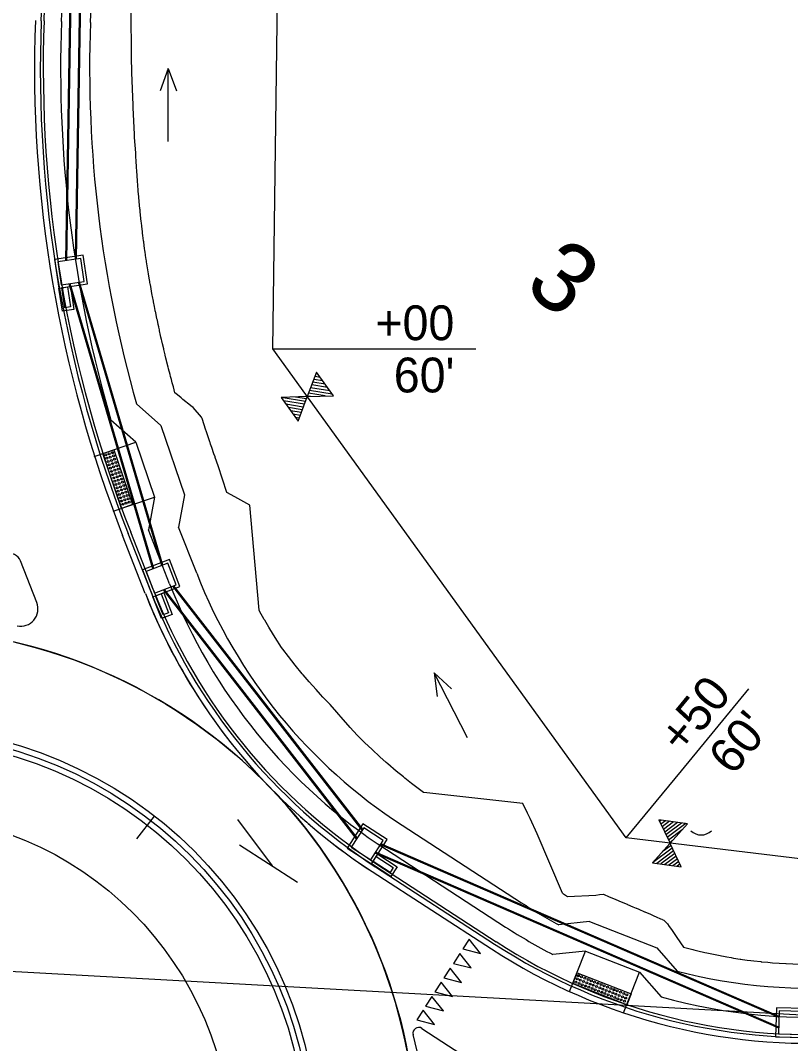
# Model space of a CAD drawing. Extents: x 670017 to 673226, y 705371 to 707498.
# Drawn here: x 671748.4 to 671881.1, y 706559.8 to 706736.1 of the extents above; entities that cross this region are included whole.
import ezdxf

# ---------------------------------------------------------------- set-up
doc = ezdxf.new("R2010")
doc.units = 0
for name, color, linetype in [('EL L 264', 7, 'Continuous'), ('EL R SCBV', 7, 'Continuous'), ('R_Drainage Flow Lines', 7, 'Continuous'), ('R_Drainage Stage 1', 7, 'Continuous'), ('R_Fence', 7, 'Continuous'), ('R_Horz Alg', 7, 'Continuous'), ('R_Horz Alg Station', 7, 'Continuous'), ('R_Horz Alg Station Annot', 7, 'Continuous'), ('R_No Plot', 7, 'Continuous'), ('R_No Plot FOC', 7, 'Continuous'), ('R_Proposed Const Limits', 7, 'Continuous'), ('R_Proposed Median', 7, 'Continuous'), ('R_Proposed RAB', 7, 'Continuous'), ('R_Proposed Road', 7, 'Continuous'), ('R_Proposed Sidewalk Stage 1', 7, 'Continuous'), ('R_ROW', 7, 'Continuous'), ('R_ROW Annot', 7, 'Continuous'), ('R_Striping', 7, 'Continuous'), ('R_Water Annot', 7, 'Continuous'), ('S_EXIST_ROW', 7, 'Continuous'), ('SS-EX-UT', 7, 'Continuous')]:
    doc.layers.add(name, color=color, linetype=linetype)

# ---------------------------------------------------------------- blocks, each defined once
blk = doc.blocks.new('FLOW ARROW')
at = {"layer": 'R_Water Annot'}
for p, q in [((-12.57, 0), (0, 0)), ((0, 0), (-3.85, 1.4)), ((0, 0), (-3.85, -1.4))]:
    blk.add_line(p, q, dxfattribs=at)

msp = doc.modelspace()

# ---------------------------------------------------------------- linework, layer by layer
at = {"layer": 'EL L 264'}
msp.add_line((671809.03, 706589.42), (671829.59, 706576.08), dxfattribs=at)
msp.add_line((671809.03, 706589.42), (671829.59, 706576.08), dxfattribs=at)
for centre, radius, start, end in [((671726.73, 706541.35), 90, 43.8918, 132.897), ((671726.73, 706541.35), 90, 43.8918, 132.897), ((671864, 706674.16), 101, 224.1964, 237.03), ((671864, 706674.16), 101, 224.1964, 237.03), ((671884.56, 706660.82), 101, 237.03, 275.3546), ((671884.56, 706660.82), 101, 237.03, 275.3546)]:
    msp.add_arc(centre, radius, start, end, dxfattribs=at)
at = {"layer": 'EL R SCBV'}
msp.add_line((671769.94, 706637.36), (671766.03, 706647.34), dxfattribs=at)
for centre, radius, start, end in [((671971.84, 706727.86), 221, 177.8657, 201.3677), ((671864, 706674.16), 101, 201.3677, 223.9093), ((671726.73, 706541.35), 90, 310.6243, 44.214)]:
    msp.add_arc(centre, radius, start, end, dxfattribs=at)
at = {"layer": 'R_Drainage Stage 1'}
for p, q in [((671756.25, 706694.69), (671759.68, 706898.95)), ((671756.42, 706694.71), (671759.85, 706898.95)), ((671757.92, 706694.94), (671761.34, 706898.93)), ((671758.09, 706694.97), (671761.51, 706898.93)), ((671772.96, 706642.24), (671758.62, 706691)), ((671771.25, 706641.57), (671756.79, 706690.72)), ((671771.4, 706641.63), (671756.96, 706690.75)), ((671772.8, 706642.18), (671758.45, 706690.98)), ((671807.32, 706596.55), (671774.68, 706638.62)), ((671807.42, 706596.7), (671774.84, 706638.68)), ((671806.36, 706595.07), (671773.06, 706637.99)), ((671806.46, 706595.22), (671773.22, 706638.05)), ((671879.17, 706564.25), (671810.46, 706594.04)), ((671879.18, 706564.43), (671810.55, 706594.18)), ((671879.12, 706562.45), (671809.54, 706592.62)), ((671879.12, 706562.63), (671809.63, 706592.76))]:
    msp.add_line(p, q, dxfattribs=at)
for points in [[(671759.99, 706690.71), (671759.23, 706695.65), (671754.29, 706694.89), (671755.05, 706689.95)], [(671759.42, 706691.13), (671758.81, 706695.08), (671754.86, 706694.47), (671755.46, 706690.52)], [(671757.02, 706690.25), (671757.63, 706686.3), (671755.65, 706685.99), (671755.05, 706689.95)], [(671756.53, 706690.18), (671757.06, 706686.72), (671756.07, 706686.56), (671755.54, 706690.02)], [(671775.91, 706638.56), (671774.09, 706643.22), (671769.43, 706641.4), (671771.25, 706636.74)], [(671775.26, 706638.85), (671773.8, 706642.57), (671770.08, 706641.12), (671771.54, 706637.39)], [(671773.12, 706637.47), (671774.57, 706633.75), (671772.71, 706633.02), (671771.25, 706636.74)], [(671772.65, 706637.29), (671773.92, 706634.03), (671772.99, 706633.67), (671771.72, 706636.92)], [(671804.73, 706593.47), (671808.92, 706590.75), (671811.64, 706594.95), (671807.45, 706597.67)], [(671805.42, 706593.62), (671808.78, 706591.44), (671810.95, 706594.8), (671807.6, 706596.97)], [(671810.01, 706592.43), (671813.37, 706590.25), (671812.28, 706588.57), (671808.92, 706590.75)], [(671809.74, 706592.01), (671812.68, 706590.1), (671812.13, 706589.27), (671809.2, 706591.17)], [(671883.72, 706565.8), (671878.72, 706565.95), (671878.57, 706560.96), (671883.57, 706560.8)], [(671883.21, 706565.31), (671879.21, 706565.44), (671879.08, 706561.44), (671883.08, 706561.32)]]:
    msp.add_lwpolyline(points, close=True, dxfattribs=at)
at = {"layer": 'R_Fence'}
for p, q in [((671799.69, 706675.13), (671799.32, 706675.19)), ((671800.93, 706673.41), (671798.79, 706673.76)), ((671800.52, 706673.98), (671798.96, 706674.23)), ((671800.11, 706674.55), (671799.14, 706674.71)), ((671800.95, 706671.38), (671798.07, 706671.85)), ((671802.17, 706671.69), (671798.25, 706672.32)), ((671801.76, 706672.26), (671798.43, 706672.8)), ((671801.34, 706672.83), (671798.61, 706673.28)), ((671797.53, 706670.42), (671793.35, 706671.1)), ((671797.35, 706669.94), (671793.77, 706670.52)), ((671797.17, 706669.46), (671794.18, 706669.95)), ((671797.71, 706670.89), (671795.85, 706671.2)), ((671798.4, 706671.29), (671797.89, 706671.37)), ((671796.99, 706668.98), (671794.59, 706669.37)), ((671796.81, 706668.51), (671795.01, 706668.8)), ((671796.64, 706668.03), (671795.42, 706668.23)), ((671796.46, 706667.55), (671795.83, 706667.65)), ((671796.28, 706667.07), (671796.24, 706667.08)), ((671858.88, 706598.3), (671858.58, 706598.07)), ((671859.58, 706598.19), (671858.8, 706597.61)), ((671860.28, 706598.09), (671859.02, 706597.15)), ((671860.98, 706597.99), (671859.24, 706596.69)), ((671861.68, 706597.89), (671859.46, 706596.23)), ((671862.38, 706597.79), (671859.67, 706595.77)), ((671863.08, 706597.69), (671859.89, 706595.31)), ((671862.45, 706596.6), (671860.11, 706594.85)), ((671860.75, 706594.7), (671860.33, 706594.39)), ((671860.77, 706593.47), (671857.38, 706590.94)), ((671860.99, 706593.01), (671858.08, 706590.83)), ((671861.21, 706592.55), (671858.78, 706590.73)), ((671860.55, 706593.93), (671859.04, 706592.8)), ((671861.43, 706592.09), (671859.48, 706590.63)), ((671861.65, 706591.63), (671860.18, 706590.53)), ((671861.87, 706591.17), (671860.88, 706590.43)), ((671862.08, 706590.71), (671861.58, 706590.33)), ((671862.3, 706590.24), (671862.28, 706590.23))]:
    msp.add_line(p, q, dxfattribs=at)
for points in [[(671797.85, 706671.26), (671797.86, 706671.27), (671802.36, 706671.43), (671799.43, 706675.49), (671797.85, 706671.27), (671797.84, 706671.27), (671793.35, 706671.11), (671796.27, 706667.05), (671797.85, 706671.26)], [(671860.38, 706594.28), (671860.39, 706594.3), (671863.39, 706597.64), (671858.44, 706598.36), (671860.38, 706594.3), (671860.37, 706594.28), (671857.37, 706590.94), (671862.32, 706590.22), (671860.38, 706594.28)]]:
    msp.add_lwpolyline(points, dxfattribs=at)
at = {"layer": 'R_Horz Alg'}
msp.add_circle((671726.73, 706541.35), 73, dxfattribs=at)
at = {"layer": 'R_Horz Alg Station'}
msp.add_lwpolyline([(671768.45, 706595.04), (671771.52, 706598.99)], dxfattribs=at)
at = {"layer": 'R_No Plot'}
for p, q in [((671785.8, 706598.37), (671791.79, 706590.43)), ((671786.2, 706594.05), (671796.16, 706587.59))]:
    msp.add_line(p, q, dxfattribs=at)
msp.add_lwpolyline([(672600.73, 706535.93), (672600.73, 706535.93), (672146.36, 706559.78), (671852.81, 706595.21), (671791.92, 706679.49), (671797.39, 707089.58)], dxfattribs=at)
msp.add_circle((671726.73, 706541.35), 90, dxfattribs=at)
at = {"layer": 'R_No Plot FOC'}
for p, q in [((671751.99, 706736.05), (671758.13, 706900.68)), ((671770.87, 706637.72), (671766.96, 706647.7)), ((671809.63, 706590.22), (671830.14, 706576.92))]:
    msp.add_line(p, q, dxfattribs=at)
msp.add_circle((671726.73, 706541.35), 72, dxfattribs=at)
for centre, radius, start, end in [((671971.84, 706727.86), 220, 177.8657, 201.3677), ((671864, 706674.16), 100, 201.3677, 237.03), ((671884.56, 706660.82), 100, 237.03, 275.3546)]:
    msp.add_arc(centre, radius, start, end, dxfattribs=at)
at = {"layer": 'R_Proposed Const Limits'}
for points in [[(671775.05, 706671.9), (671774.77, 706672.94), (671774.67, 706673.32), (671774.58, 706673.63), (671774.43, 706674.23), (671774.3, 706674.71), (671774.29, 706674.74), (671774.2, 706675.08), (671773.96, 706676.04), (671773.95, 706676.1), (671773.89, 706676.32), (671773.67, 706677.22), (671773.6, 706677.51), (671773.5, 706677.92), (671773.37, 706678.43), (671773.37, 706678.46), (671773.25, 706678.93), (671773.15, 706679.37), (671773.11, 706679.52), (671772.91, 706680.35), (671772.79, 706680.89), (671772.73, 706681.14), (671772.64, 706681.53), (671772.58, 706681.78), (671772.4, 706682.62), (671772.36, 706682.78), (671772.26, 706683.23), (671772.24, 706683.32), (671772.16, 706683.69), (671772.01, 706684.42), (671771.95, 706684.68), (671771.73, 706685.76), (671771.71, 706685.86), (671771.66, 706686.08), (671771.65, 706686.13), (671771.52, 706686.81), (671771.36, 706687.59), (671771.33, 706687.74), (671771.28, 706688.03), (671771.24, 706688.21), (671771.08, 706689.06), (671771.01, 706689.42), (671770.87, 706690.22), (671770.81, 706690.53), (671770.79, 706690.67), (671770.73, 706691), (671770.71, 706691.11), (671770.66, 706691.41), (671770.55, 706692.01), (671770.48, 706692.4), (671770.42, 706692.8), (671770.36, 706693.14), (671770.3, 706693.49), (671770.14, 706694.51), (671770.12, 706694.6), (671770.07, 706694.97), (671770.04, 706695.2), (671769.98, 706695.63), (671769.9, 706696.23), (671769.88, 706696.34), (671769.87, 706696.45), (671769.82, 706696.8), (671769.75, 706697.29), (671769.67, 706697.95), (671769.64, 706698.12), (671769.53, 706699.02), (671769.48, 706699.41), (671769.44, 706699.69), (671769.33, 706700.62), (671769.26, 706701.23), (671769.24, 706701.42), (671769.06, 706703.13), (671769.06, 706703.17), (671769.03, 706703.45), (671769.01, 706703.62), (671768.88, 706704.92), (671768.81, 706705.65), (671768.81, 706705.68), (671768.72, 706706.67), (671768.63, 706707.85), (671768.62, 706707.92), (671768.6, 706708.18), (671768.58, 706708.44), (671768.58, 706708.48), (671768.47, 706710.16), (671768.46, 706710.2), (671768.43, 706710.73), (671768.35, 706711.97), (671768.35, 706712.09), (671768.33, 706712.4), (671768.28, 706713.28), (671768.1, 706715.94), (671768.07, 706716.5), (671767.95, 706718.72), (671767.84, 706721.12), (671767.82, 706721.51), (671767.71, 706724.3), (671767.66, 706725.75), (671767.63, 706727.09), (671767.56, 706729.88), (671767.56, 706730.37), (671767.53, 706732.68), (671767.51, 706735), (671767.51, 706735.48), (671767.54, 706739.96)], [(671784, 706654.76), (671782.47, 706659.33), (671781.98, 706660.78), (671781.95, 706660.87), (671781.77, 706661.39), (671781.39, 706662.52), (671781.2, 706663.09), (671781.11, 706663.35), (671781.08, 706663.45), (671780.42, 706665.4), (671780.38, 706665.51), (671779.72, 706667.47), (671779.68, 706667.56), (671779.64, 706667.71), (671778.18, 706669.37), (671777.78, 706669.69), (671777.75, 706669.72), (671776.42, 706670.79), (671776.24, 706670.94), (671776.11, 706671.04), (671775.46, 706671.57), (671775.05, 706671.9)], [(671841.82, 706585.71), (671837.48, 706595.94), (671836.26, 706598.57), (671835.82, 706599.49), (671834.98, 706601.17), (671817.93, 706603.02), (671817.91, 706603.04), (671816.25, 706604.28), (671815.81, 706604.62), (671814.68, 706605.51), (671814.41, 706605.73), (671813.17, 706606.75), (671811.73, 706607.98), (671811.46, 706608.22), (671810.35, 706609.21), (671809.01, 706610.45), (671807.71, 706611.69), (671807.57, 706611.84), (671806.45, 706612.95), (671805.26, 706614.25), (671804.09, 706615.56), (671804.05, 706615.61), (671802.95, 706616.89), (671801.78, 706618.19), (671800.61, 706619.42), (671800.56, 706619.47), (671800.12, 706619.95), (671799.36, 706620.78), (671798.16, 706622.13), (671797.12, 706623.35), (671796.97, 706623.52), (671795.79, 706624.97), (671794.61, 706626.47), (671793.66, 706627.72), (671793.43, 706628.04), (671792.32, 706629.73), (671791.39, 706631.26), (671791.24, 706631.51), (671790.53, 706632.72), (671790.45, 706632.86), (671790.15, 706633.39), (671789.7, 706634.2), (671789.55, 706634.46), (671787.95, 706652.54), (671785.36, 706654.02), (671784, 706654.76)], [(671841.82, 706585.71), (671842.73, 706585.13), (671847.57, 706585.35), (671848.2, 706585.46), (671848.89, 706585.5), (671849.91, 706585.07), (671850.93, 706584.65), (671851.54, 706584.39), (671851.55, 706584.39), (671851.95, 706584.22), (671852.96, 706583.79), (671853.06, 706583.75), (671853.97, 706583.36), (671854.55, 706583.11), (671854.61, 706583.09), (671854.98, 706582.93), (671855.99, 706582.5), (671856.03, 706582.48), (671856.99, 706582.06), (671857.49, 706581.84), (671857.58, 706581.81), (671858, 706581.62), (671858.75, 706581.3), (671858.95, 706581.21), (671859.01, 706581.18), (671859.33, 706581.04), (671859.83, 706580.53), (671859.92, 706580.41), (671860.23, 706579.96), (671860.29, 706579.87), (671860.72, 706579.25), (671861.41, 706578.25), (671861.55, 706578.05), (671862.68, 706576.42)], [(671862.68, 706576.42), (671864.31, 706575.99), (671864.49, 706575.95), (671865.61, 706575.67), (671865.93, 706575.59), (671866.36, 706575.49), (671866.73, 706575.41), (671867.56, 706575.23), (671867.87, 706575.16), (671869.01, 706574.93), (671869.22, 706574.89), (671869.58, 706574.82), (671870.16, 706574.72), (671870.9, 706574.59), (671871.31, 706574.52), (671872.47, 706574.34), (671872.6, 706574.32), (671872.85, 706574.28), (671873.65, 706574.17), (671874.32, 706574.09), (671874.83, 706574.03), (671876.02, 706573.9), (671876.08, 706573.89), (671876.21, 706573.88), (671877.21, 706573.78), (671878.06, 706573.72), (671880.33, 706573.58), (671880.37, 706573.58), (671882.68, 706573.48)]]:
    msp.add_lwpolyline(points, dxfattribs=at)
at = {"layer": 'R_Proposed Median'}
for p, q in [((671751.22, 706635.79), (671748.42, 706642.96)), ((671817.61, 706562.4), (671829.92, 706554.42))]:
    msp.add_line(p, q, dxfattribs=at)
for centre, radius, start, end in [((671746.56, 706642.23), 2, 21.3677, 108.9101), ((671748.43, 706634.7), 3, 258.4277, 21.3677), ((671817.07, 706561.56), 1, 57.03, 194.2896), ((671727.43, 706538.73), 91.5, 345.3135, 14.2896)]:
    msp.add_arc(centre, radius, start, end, dxfattribs=at)
at = {"layer": 'R_Proposed RAB'}
for radius in [71, 58]:
    msp.add_circle((671726.73, 706541.35), radius, dxfattribs=at)
at = {"layer": 'R_Proposed Road'}
for p, q in [((671752.49, 706736.04), (671758.63, 706900.66)), ((671769.94, 706637.36), (671766.03, 706647.34)), ((671771.34, 706637.9), (671767.43, 706647.89)), ((671809.85, 706590.68), (671830.41, 706577.34)), ((671809.03, 706589.42), (671829.59, 706576.08))]:
    msp.add_line(p, q, dxfattribs=at)
for centre, radius, start, end in [((671971.84, 706727.86), 221, 177.8657, 201.3677), ((671971.84, 706727.86), 219.5, 177.8657, 201.3677), ((671864, 706674.16), 101, 201.3677, 237.03), ((671864, 706674.16), 99.5, 201.3677, 237.03), ((671884.56, 706660.82), 99.5, 237.03, 275.3546), ((671884.56, 706660.82), 101, 237.03, 275.3546)]:
    msp.add_arc(centre, radius, start, end, dxfattribs=at)
at = {"layer": 'R_Proposed Sidewalk Stage 1'}
for p, q in [((671755.49, 706735.92), (671761.63, 706900.65)), ((671760.49, 706735.74), (671766.63, 706900.57)), ((671772.6, 706666.28), (671768.41, 706670.01)), ((671768.3, 706663.42), (671764, 706667.23)), ((671772.6, 706666.28), (671776.69, 706654.33)), ((671761.15, 706660.97), (671768.3, 706663.42)), ((671768.3, 706663.42), (671771.54, 706653.96)), ((671764.51, 706662.12), (671767.75, 706652.66)), ((671776.69, 706654.33), (671775.66, 706648.8)), ((671764.39, 706651.51), (671771.54, 706653.96)), ((671771.54, 706653.96), (671770.48, 706648.31)), ((671778.79, 706640.82), (671775.66, 706648.8)), ((671774.13, 706639), (671770.48, 706648.31)), ((671814.2, 706597.39), (671834.76, 706584.05)), ((671811.48, 706593.2), (671832.04, 706579.86)), ((671846.49, 706580.82), (671841.18, 706580.25)), ((671846.49, 706580.82), (671858.08, 706576.27)), ((671845.81, 706575.72), (671840.2, 706575.12)), ((671843.07, 706568.73), (671845.81, 706575.72)), ((671845.81, 706575.72), (671855.12, 706572.07)), ((671858.08, 706576.27), (671861.59, 706572.25)), ((671844.35, 706571.99), (671853.66, 706568.34)), ((671852.38, 706565.08), (671855.12, 706572.07)), ((671855.12, 706572.07), (671858.82, 706567.81))]:
    msp.add_line(p, q, dxfattribs=at)
for points in [[(671764.51, 706662.12), (671767.75, 706652.66), (671765.86, 706652.01), (671762.62, 706661.47)], [(671844.35, 706571.99), (671853.66, 706568.34), (671852.92, 706566.48), (671843.62, 706570.13)]]:
    msp.add_lwpolyline(points, close=True, dxfattribs=at)
for centre in [(671763.13, 706661.23), (671763.7, 706661.42), (671763.89, 706660.85), (671764.26, 706661.61), (671764.46, 706661.05), (671763.32, 706660.66), (671763.52, 706660.09), (671763.71, 706659.52), (671764.09, 706660.28), (671764.28, 706659.72), (671764.47, 706659.15), (671764.65, 706660.48), (671764.85, 706659.91), (671765.04, 706659.34), (671763.91, 706658.95), (671764.1, 706658.39), (671764.3, 706657.82), (671764.67, 706658.58), (671764.86, 706658.01), (671765.06, 706657.45), (671765.24, 706658.78), (671765.43, 706658.21), (671765.63, 706657.64), (671764.49, 706657.25), (671764.69, 706656.68), (671764.88, 706656.12), (671765.25, 706656.88), (671765.45, 706656.31), (671765.64, 706655.74), (671765.82, 706657.07), (671766.01, 706656.51), (671766.21, 706655.94), (671765.07, 706655.55), (671765.27, 706654.98), (671765.46, 706654.41), (671765.66, 706653.85), (671765.84, 706655.18), (671766.03, 706654.61), (671766.22, 706654.04), (671766.4, 706655.37), (671766.6, 706654.8), (671766.79, 706654.24), (671765.85, 706653.28), (671766.05, 706652.71), (671766.42, 706653.47), (671766.61, 706652.91), (671766.99, 706653.67), (671767.18, 706653.1), (671844.57, 706571.48), (671845.13, 706571.26), (671845.69, 706571.04), (671844.13, 706570.36), (671844.35, 706570.92), (671844.69, 706570.14), (671844.91, 706570.7), (671845.25, 706569.92), (671845.47, 706570.48), (671845.81, 706569.7), (671846.03, 706570.26), (671846.25, 706570.82), (671846.37, 706569.48), (671846.59, 706570.04), (671846.81, 706570.6), (671846.93, 706569.26), (671847.15, 706569.82), (671847.36, 706570.38), (671847.7, 706569.6), (671847.92, 706570.16), (671848.26, 706569.38), (671848.48, 706569.94), (671849.04, 706569.72), (671849.6, 706569.5), (671850.16, 706569.28), (671847.49, 706569.04), (671848.04, 706568.82), (671848.6, 706568.61), (671848.82, 706569.16), (671849.16, 706568.39), (671849.38, 706568.94), (671849.72, 706568.17), (671849.94, 706568.73), (671850.28, 706567.95), (671850.5, 706568.51), (671850.72, 706569.07), (671850.84, 706567.73), (671851.06, 706568.29), (671851.27, 706568.85), (671851.4, 706567.51), (671851.61, 706568.07), (671851.83, 706568.63), (671852.17, 706567.85), (671852.39, 706568.41), (671852.73, 706567.63), (671852.95, 706568.19), (671851.95, 706567.29), (671852.51, 706567.07)]:
    msp.add_circle(centre, 0.165, dxfattribs=at)
for centre, radius, start, end in [((671971.84, 706727.86), 216.5, 177.8657, 196.2627), ((671971.84, 706727.86), 211.5, 177.8657, 195.8748), ((671864, 706674.16), 91.5, 201.3677, 237.03), ((671864, 706674.16), 96.5, 201.3677, 237.03), ((671884.56, 706660.82), 91.5, 237.03, 241.7045), ((671884.56, 706660.82), 96.5, 237.03, 242.6348), ((671884.56, 706660.82), 91.5, 255.4612, 275.3546), ((671884.56, 706660.82), 96.5, 254.5309, 275.3546)]:
    msp.add_arc(centre, radius, start, end, dxfattribs=at)
at = {"layer": 'R_ROW'}
msp.add_lwpolyline([(672600.73, 706535.93), (672600.73, 706535.93), (672146.36, 706559.78), (671852.81, 706595.21), (671791.92, 706679.49), (671797.39, 707089.58)], dxfattribs=at)
at = {"layer": 'R_ROW Annot'}
for points in [[(671791.92, 706679.49), (671806.92, 706679.49), (671826.92, 706679.49)], [(671852.81, 706595.21), (671862.34, 706606.8), (671873.96, 706620.94)]]:
    msp.add_lwpolyline(points, dxfattribs=at)
at = {"layer": 'R_Striping'}
for points in [[(671825.75, 706577.8), (671824.66, 706576.12), (671827.72, 706575.33), (671825.75, 706577.8)], [(671827.72, 706575.33), (671825.75, 706577.8)], [(671824.12, 706575.28), (671823.03, 706573.6), (671826.09, 706572.81), (671824.12, 706575.28)], [(671826.09, 706572.81), (671824.12, 706575.28)], [(671824.66, 706576.12), (671827.72, 706575.33)], [(671823.03, 706573.6), (671826.09, 706572.81)], [(671822.48, 706572.77), (671821.4, 706571.09), (671824.46, 706570.29), (671822.48, 706572.77)], [(671824.46, 706570.29), (671822.48, 706572.77)], [(671822.89, 706567.87), (671820.92, 706570.34), (671819.83, 706568.67), (671822.89, 706567.87)], [(671822.89, 706567.87), (671820.92, 706570.34)], [(671821.4, 706571.09), (671824.46, 706570.29)], [(671819.34, 706567.91), (671818.25, 706566.23), (671821.31, 706565.44), (671819.34, 706567.91)], [(671821.31, 706565.44), (671819.34, 706567.91)], [(671819.83, 706568.67), (671822.89, 706567.87)], [(671818.25, 706566.23), (671821.31, 706565.44)], [(671817.82, 706565.56), (671816.73, 706563.88), (671819.79, 706563.09), (671817.82, 706565.56)], [(671819.79, 706563.09), (671817.82, 706565.56)], [(671816.73, 706563.88), (671819.79, 706563.09)]]:
    msp.add_lwpolyline(points, dxfattribs=at)
at = {"layer": 'S_EXIST_ROW'}
msp.add_lwpolyline([(670020.59, 706668.53), (670619.99, 706639.58), (670619.86, 706634.58), (671728.16, 706573.3), (673225.88, 706490.48)], dxfattribs=at)
at = {"layer": 'SS-EX-UT'}
msp.add_arc((671865.73, 706598.23), 2.5, 225.1611, 315.1611, dxfattribs=at)

# ---------------------------------------------------------------- block references
at = {"layer": 'R_Drainage Flow Lines'}
for p, rotation in [((671773.89, 706727.81), 89.99999999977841), ((671819.73, 706623.67), 117.15978551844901)]:
    msp.add_blockref('FLOW ARROW', p, dxfattribs=dict(at, rotation=rotation))

# ---------------------------------------------------------------- texts
at = {"layer": 'R_Horz Alg Station Annot'}
msp.add_text('3', height=12, rotation=322.148, dxfattribs=at).set_placement((671834.91, 706689.84))
at = {"layer": 'R_ROW Annot'}
for s, rotation, p in [('+00', 360, (671809.59, 706680.99)), ("60'", 360, (671812.76, 706671.99)), ('+50', 50.5773, (671862.54, 706609.41)), ("60'", 50.5773, (671871.21, 706605.78))]:
    msp.add_text(s, height=6, rotation=rotation, dxfattribs=at).set_placement(p)

doc.saveas('drawing.dxf')
